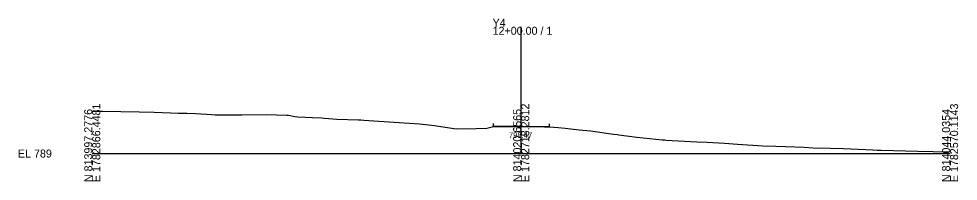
# Model space of a CAD drawing. Extents: x -26 to 3903, y -10 to 9562.
# Drawn here: x -25.7 to 302.8, y 3990.3 to 4047.2 of the extents above; entities that cross this region are included whole.
import ezdxf

# ---------------------------------------------------------------- set-up
doc = ezdxf.new("R2010")
doc.units = 0
for name, color, linetype in [('Exist Cross Section Cell', 7, 'Continuous'), ('Exist XS Center Line Elevation Label', 7, 'Continuous'), ('Exist XS Ground Line', 7, 'Continuous'), ('Prop XS EOT Tick Mark', 7, 'Continuous'), ('Prop XS Finish Grade Pavement', 7, 'Continuous')]:
    doc.layers.add(name, color=color, linetype=linetype)

msp = doc.modelspace()

# ---------------------------------------------------------------- linework, layer by layer
at = {"layer": 'Exist Cross Section Cell'}
for p, q in [((150, 4000), (150, 4044.37)), ((0, 4000), (150, 4000)), ((150, 4000), (300, 4000))]:
    msp.add_line(p, q, dxfattribs=at)
at = {"layer": 'Exist XS Ground Line'}
for p, q in [((0, 4014.78), (1.16, 4014.79)), ((1.16, 4014.79), (3.61, 4014.78)), ((3.61, 4014.78), (16.35, 4014.63)), ((16.35, 4014.63), (21.62, 4014.43)), ((21.62, 4014.43), (30.21, 4014.09)), ((30.21, 4014.09), (33.06, 4014.13)), ((33.06, 4014.13), (36.16, 4014.07)), ((36.16, 4014.07), (41.85, 4013.62)), ((41.85, 4013.62), (43, 4013.54)), ((43, 4013.54), (44.41, 4013.55)), ((44.41, 4013.55), (52.29, 4013.6)), ((52.29, 4013.6), (60.77, 4013.62)), ((60.77, 4013.62), (64.48, 4013.6)), ((64.48, 4013.6), (68.1, 4013.47)), ((68.1, 4013.47), (68.58, 4013.4)), ((68.58, 4013.4), (70.84, 4012.99)), ((70.84, 4012.99), (71.93, 4012.86)), ((71.93, 4012.86), (76.97, 4012.63)), ((76.97, 4012.63), (80.13, 4012.51)), ((80.13, 4012.51), (81.25, 4012.41)), ((81.25, 4012.41), (85.55, 4012.04)), ((85.55, 4012.04), (93.07, 4011.8)), ((93.07, 4011.8), (93.91, 4011.77)), ((93.91, 4011.77), (94.99, 4011.69)), ((94.99, 4011.69), (107.29, 4010.82)), ((107.29, 4010.82), (114.45, 4010.34)), ((114.45, 4010.34), (117.6, 4010.1)), ((117.6, 4010.1), (119.73, 4009.87)), ((119.73, 4009.87), (123.39, 4009.27)), ((123.39, 4009.27), (127.21, 4008.59)), ((127.21, 4008.59), (134.23, 4008.72)), ((134.23, 4008.72), (138.01, 4008.88)), ((138.01, 4008.88), (138.91, 4009.07)), ((138.91, 4009.07), (140.3, 4009.42)), ((140.3, 4009.42), (146.65, 4009.44)), ((146.65, 4009.44), (150.01, 4009.47)), ((150.01, 4009.47), (158.15, 4009.32)), ((158.15, 4009.32), (159.91, 4009.29)), ((159.91, 4009.29), (162.88, 4009.07)), ((162.88, 4009.07), (165.34, 4008.88)), ((165.34, 4008.88), (170.3, 4008.35)), ((170.3, 4008.35), (174.25, 4007.91)), ((174.25, 4007.91), (182.3, 4006.83)), ((182.3, 4006.83), (183.55, 4006.67)), ((183.55, 4006.67), (184.11, 4006.58)), ((184.11, 4006.58), (190.48, 4005.68)), ((190.48, 4005.68), (199.25, 4004.83)), ((199.25, 4004.83), (199.83, 4004.78)), ((199.83, 4004.78), (200.23, 4004.75)), ((200.23, 4004.75), (200.73, 4004.72)), ((200.73, 4004.72), (211.41, 4004.12)), ((211.41, 4004.12), (215.07, 4003.94)), ((215.07, 4003.94), (221.12, 4003.58)), ((221.12, 4003.58), (225.69, 4003.31)), ((225.69, 4003.31), (234.57, 4002.75)), ((234.57, 4002.75), (239.09, 4002.53)), ((239.09, 4002.53), (248.98, 4002.19)), ((248.98, 4002.19), (252.09, 4002.02)), ((252.09, 4002.02), (258.02, 4001.9)), ((258.02, 4001.9), (262.67, 4001.78)), ((262.67, 4001.78), (272.96, 4001.29)), ((272.96, 4001.29), (274.5, 4001.22)), ((274.5, 4001.22), (275.94, 4001.17)), ((275.94, 4001.17), (288.7, 4000.83)), ((288.7, 4000.83), (294.06, 4000.7)), ((294.06, 4000.7), (300, 4000.63))]:
    msp.add_line(p, q, dxfattribs=at)
at = {"layer": 'Prop XS EOT Tick Mark'}
for p, q in [((140.3, 4009.55), (140.3, 4010.55)), ((159.91, 4009.41), (159.91, 4010.41))]:
    msp.add_line(p, q, dxfattribs=at)
at = {"layer": 'Prop XS Finish Grade Pavement'}
for p, q in [((140.3, 4009.55), (146.65, 4009.57)), ((146.65, 4009.57), (150.01, 4009.6)), ((150.01, 4009.6), (158.15, 4009.44)), ((158.15, 4009.44), (159.91, 4009.41))]:
    msp.add_line(p, q, dxfattribs=at)

# ---------------------------------------------------------------- texts
at = {"layer": 'Exist Cross Section Cell'}
for s, p in [('Y4', (140, 4044.37)), ('12+00.00 / 1', (140, 4041.57)), ('EL 789', (-26, 3998.6))]:
    msp.add_text(s, height=2.8, dxfattribs=at).set_placement(p)
for s, p in [('N 813997.2776', (0, 3990)), ('E 1782866.4481', (2.8, 3990)), ('N 814020.6565', (150, 3990)), ('E 1782718.2812', (152.8, 3990)), ('N 814044.0354', (300, 3990)), ('E 1782570.1143', (302.8, 3990))]:
    msp.add_text(s, height=2.8, rotation=90, dxfattribs=at).set_placement(p)
at = {"layer": 'Exist XS Center Line Elevation Label'}
msp.add_text('798.47', height=2, dxfattribs=at).set_placement((145.7, 4005.47))

doc.saveas('drawing.dxf')
